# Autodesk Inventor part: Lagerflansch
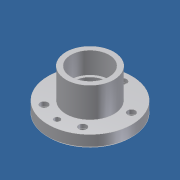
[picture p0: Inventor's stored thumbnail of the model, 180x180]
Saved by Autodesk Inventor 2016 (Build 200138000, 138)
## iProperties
Created: 2011-06
Part Number: Lagerflansch
Document SubType Name: Modeling
Designer: ch
Density: 1 g/cm^3
Material: Allgemein
Appearance: Vorgabe
Author: ch
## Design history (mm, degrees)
sketch "Skizze1"
  geometry: C1 r 35 at (0, 0); 1 further point
  constraints: 1 centre point, 1 coincident
  dimensions: "d0" = 70 diameter of C1
extrude "Extrusion1" new body sketch "Skizze1" distance "d1" = 10; taper "d2" = 0 deg
sketch "Skizze2"
  geometry: C1 r 20 at (0, 0); 1 further point
  constraints: 1 centre point, 1 coincident
  dimensions: "d3" = 40 diameter of C1
extrude "Extrusion2" join sketch "Skizze2" distance "d4" = 25; taper "d5" = 0 deg
sketch "Skizze5"
  geometry: L1 (0, 0)-(0, 27.5)
  constraints: 2 end point, 1 vertical
  dimensions: "d12" = 27.5 distance of L1.start L1.end
hole "Zapfen Ø11 mm x 6,6 mm tief, Ø6,6 mm durch_1" sketch "Skizze5" at (0, 27.5) diameter "d13" = 6.6; stored, may be unused: countersink angle "d17" = 90 deg, drill point angle "d19" = 118 deg; dims "d14" = 6, "d15" = 11, "d16" = 6.6, "d18" = 8
pattern_circular "Runde Anordnung1" dims angle "d21" = 360 deg
chamfer "Fase 1 mm_1" distance "d23" = 1; stored, may be unused: second distance "d24" = 2, angle "d25" = 45 deg
sketch "Skizze6"
  geometry: L1 (0, 0)-(0, -27.5)
  constraints: 2 end point, 1 vertical
  dimensions: "d27" = 27.5 distance of L1.start L1.end
hole "Ø5 mm durch_1" sketch "Skizze6" at (0, -27.5) diameter "d28" = 5; stored, may be unused: countersink angle "d32" = 90 deg, drill point angle "d34" = 118 deg; dims "d29" = 6, "d30" = 11, "d31" = 6.6, "d33" = 8
sketch "Skizze7"
  geometry: C1 r 16 at (0, 0); 1 further point
  constraints: 1 centre point, 1 coincident
  dimensions: "d35" = 32 diameter of C1
extrude "Extrusion5" cut sketch "Skizze7" distance "d36" = 18; taper "d37" = 0 deg
sketch "Skizze8"
  geometry: C1 r 14 at (0, 0); 1 further point
  constraints: 1 centre point, 1 coincident
  dimensions: "d38" = 28 diameter of C1
extrude "Extrusion6" cut sketch "Skizze8" distance "d39" = 11; taper "d40" = 0 deg
fillet "Radius 2 mm_1" dims "d41" = 2
node "Volumenkörper1"
